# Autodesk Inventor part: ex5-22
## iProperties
Created: 2006-03
Part Number: ex5-22
Document SubType Name: Modeling
Designer: Elise Moss
Author: Elise Moss
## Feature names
1. Extrusion1
2. Hole1
3. Hole2
4. Key Square (Hole)1 [Extrusion]
